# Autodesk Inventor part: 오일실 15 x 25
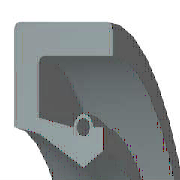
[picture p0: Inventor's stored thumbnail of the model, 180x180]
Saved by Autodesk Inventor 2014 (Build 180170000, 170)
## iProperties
IsCustomPart: 0
Created: 2015-10
Part Number: 오일실 15 x 25
Material: 고무
Description: 오일-실
Document SubType Name: Modeling
Standard: KS B 2804
Designer: mdu
Standards Organization: KS
Language: ko-KR
Size Designation: S - 15 25 7
Categories: <MemberInstance><Categories><Category DisplayName="샤프트 부품" InternalName="7f7aeb1f-a693-4053-b835-cee3144e0d98" Mnemonic="SHFT"><Category DisplayName="실링" Intern
Density: 0.93 g/cm^3
Appearance: 고무 - 검은색 - 버전 1.1
Author: mdu
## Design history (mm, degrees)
revolve "본체" stored, may be unused: angle "d17" = 90 deg
revolve "스프링1" stored, may be unused: angle "d18" = 90 deg
body "Solid1"
sketch "스케치1"
  geometry: L1 (0, 12.5)-(7, 12.5); L2 (7, 12.5)-(7, 11.25); L3 (7, 11.25)-(1.75, 11.25); L4 (0, 12.5)-(0, 9.6); L5 (0, 9.6)-(1.75, 9.25); L6 (1.75, 9.25)-(4.9, 7.5); L7 (4.9, 7.5)-(0, 7.5); L8 (6.3, 8.375)-(6.3, 9.6); L9 (0, 0)-(9.586, 0) reference; L10 (4.9, 7.5)-(6.3, 8.375); L11 (0, 18)-(0, -3) reference; L12 (-1.917, 0)-(11.503, 0) reference; L13 (4.2, 9.6)-(1.75, 10.09); L14 (1.75, 10.09)-(1.75, 11.25); L15 (6.3, 9.6)-(5.6, 9.6); C1 r 0.455 at (4.9, 9.6); A1 r 0.7 centre (4.9, 9.6) between (5.6, 9.6) and (4.2, 9.6)
  constraints: 26 end point, 5 horizontal alignment, 4 perpendicular, 2 centre point, 2 collinear, 2 horizontal, 2 parallel, 2 point on circle, 2 point on line, 2 vertical alignment, 1 coincident
  dimensions: "d0" = 25 diameter of L1 L9 (= SD2); "d1" = 16.75 diameter of L8.start L9 (= ABDM); "d2" = 1.25 distance of L1.end L2.end (computed from SD); "d3" = 0.91 diameter of C1 (= SPDI); "d4" = 1.4 diameter of A1 (= SPDA); "d5" = 15 diameter of L6.end L9 (= NND); "d6" = 18.5 diameter of L5.end L9 (= TKDM); "d7" = 19.2 diameter of L4.end L9 (= HLDM); "d8" = 4.9 distance from line of C1.centre L4 (= SPDST); "d9" = 6.3 distance between parallel lines of L8 L4 (= SDI); "d10" = 7 distance between parallel lines of L2 L4 (= SWDT); "d12" = 1.75 distance between parallel lines of L14 L4 (= SD)
fillet "모깎기1" dims "d11" = 0.3 (= RR)
other parameters: "SD2" = 25 [user parameter; used in 1 equation term], "SWDT" = 7 [user parameter; used in 1 equation term], "RR" = 0.3 [user parameter; used in 1 equation term], "SD" = 1.75 [user parameter; used in 2 equation terms], "NND" = 15 [user parameter; used in 1 equation term], "SPDA" = 1.4 [user parameter; used in 1 equation term], "SPDI" = 0.91 [user parameter; used in 1 equation term], "TKDM" = 18.5 [user parameter; used in 1 equation term], "HLDM" = 19.2 [user parameter; used in 1 equation term], "ABDM" = 16.75 [user parameter; used in 1 equation term], "SDI" = 6.3 [user parameter; used in 1 equation term], "SPDST" = 4.9 [user parameter; used in 1 equation term], "d13" = 0, "d14" = 0, "d15" = 0, "LAB" = 0.35 [user parameter]
